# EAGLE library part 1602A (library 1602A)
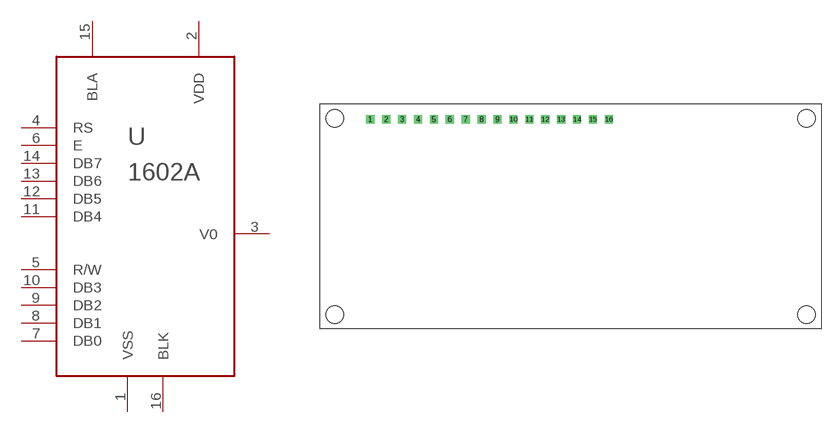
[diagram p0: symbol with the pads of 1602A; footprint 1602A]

Designator prefix -

## 1602A  [1602A]
1  VSS
2  VDD
3  V0
4  RS
5  R/W
6  E
7  DB0
8  DB1
9  DB2
10  DB3
11  DB4
12  DB5
13  DB6
14  DB7
15  BLA
16  BLK

## Footprint 1602A (pad centres in mm)
drill 0.8 square: 1 -31.15,14.29; 2 -28.61,14.29; 3 -26.07,14.29; 4 -23.53,14.29; 5 -20.99,14.29; 6 -18.45,14.29; 7 -15.91,14.29; 8 -13.37,14.29; 9 -10.83,14.29; 10 -8.29,14.29; 11 -5.75,14.29; 12 -3.21,14.29; 13 -0.67,14.29; 14 1.87,14.29; 15 4.41,14.29; 16 6.95,14.29
hole 2.8 at -36.85,14.49
hole 2.8 at 38.55,14.49
hole 2.8 at 38.55,-16.91
hole 2.8 at -36.85,-16.91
